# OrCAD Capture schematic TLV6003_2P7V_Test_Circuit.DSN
size A; title: TLV6003 980-nA, 16-V, Precision, Rail-to-Rail Input and Output,; rev: 1.1; note: Datasheet:SLOS981 EVM: N/A
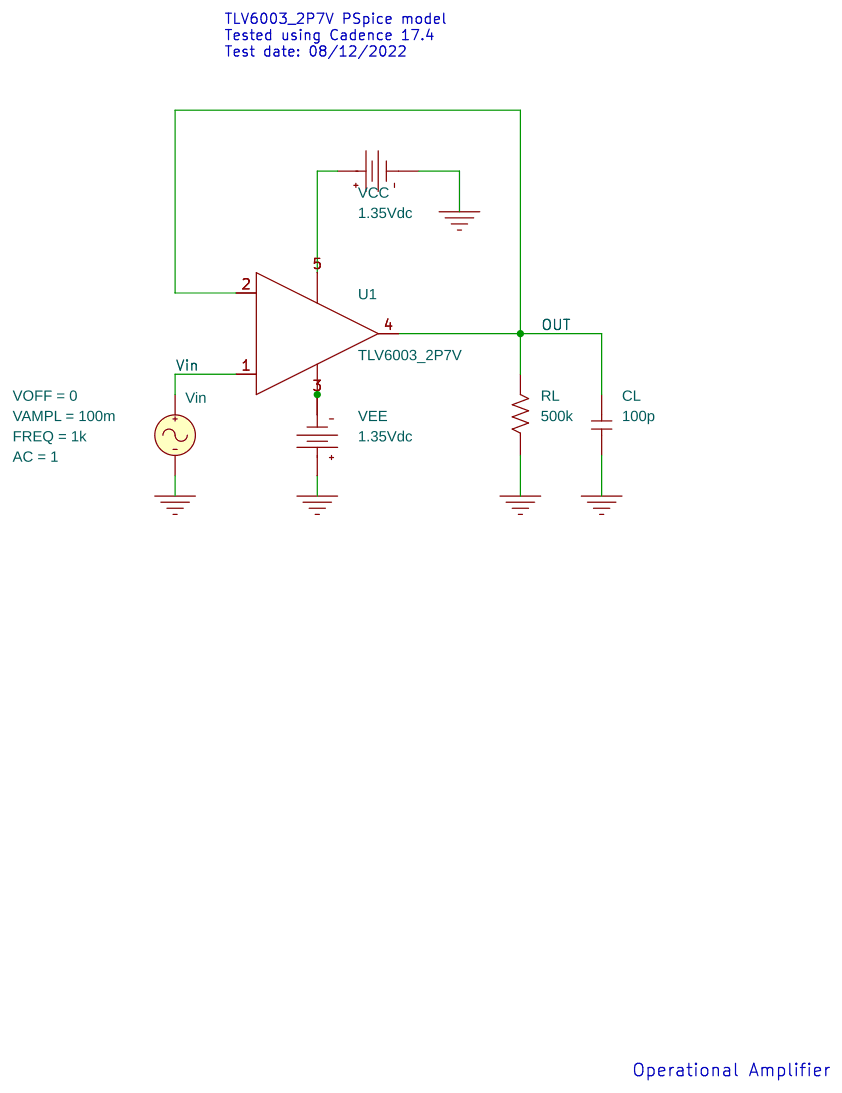
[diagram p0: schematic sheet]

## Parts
CL  100p  [RAD/CK05]
RL  500k  [AX/RC05]
U1  TLV6003_2P7V
VCC  VDC
VEE  VDC
Vin  VSIN

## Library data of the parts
CL = C
RL = R
U1 = TLV6003_2P7V
VCC VEE = VDC: DC: 1.35Vdc
Vin = VSIN: AC: 1; FREQ: 1k; VAMPL: 100m; VOFF: 0

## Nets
Vin: U1.1(+) Vin.1(+)
0: CL.1 RL.1 VCC.1(-) VEE.0(+) Vin.2(-)
OUT: CL.2 RL.2 U1.2(-) U1.4(OUT)
N22995: U1.5(V+) VCC.0(+)
N23017: U1.3(V-) VEE.1(-)

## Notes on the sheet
- TLV6003_2P7V PSpice model
  Tested using Cadence 17.4
  Test date: 08/12/2022
- Operational Amplifier
